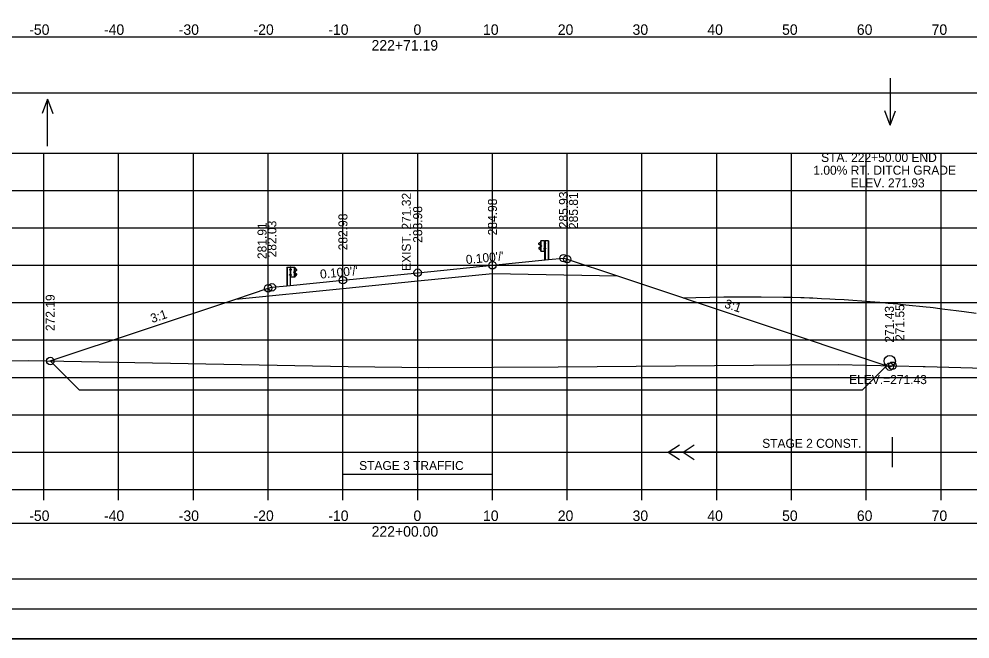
# Model space of a CAD drawing. Extents: x 4667 to 1632277, y -2100 to 724501.
# Drawn here: x 5723.9 to 5851.1, y -470.4 to -387.5 of the extents above; entities that cross this region are included whole.
import ezdxf

# ---------------------------------------------------------------- set-up
doc = ezdxf.new("R2010")
doc.units = 0
for name, color, linetype in [('R_Alt Surface', 7, 'Continuous'), ('R_Axis', 7, 'Continuous'), ('R_Axis Annot', 7, 'Continuous'), ('R_Border', 7, 'Continuous'), ('R_Draft', 7, 'Continuous'), ('R_Exist Surface', 7, 'Continuous'), ('R_Fin Surface', 7, 'Continuous'), ('R_Fin Surface Annot', 7, 'Continuous'), ('R_Grid', 7, 'Continuous'), ('R_No Plot', 7, 'Continuous'), ('R_Proposed CofA', 7, 'Continuous'), ('R_ROW', 7, 'Continuous'), ('R_Temp Easement', 7, 'Continuous'), ('R_Water', 7, 'Continuous'), ('R_Water Annot', 7, 'Continuous')]:
    doc.layers.add(name, color=color, linetype=linetype)

msp = doc.modelspace()

# ---------------------------------------------------------------- linework, layer by layer
at = {"layer": 'R_Alt Surface'}
msp.add_lwpolyline([(5752.86, -424.95), (5767.18, -423.52), (5777.18, -422.52), (5787.18, -421.52), (5803.91, -421.85)], dxfattribs=at)
at = {"layer": 'R_Axis'}
for p, q in [((5667.18, -450.42), (5947.18, -450.42)), ((5727.18, -451.82), (5727.18, -450.42)), ((5737.18, -451.82), (5737.18, -450.42)), ((5747.18, -451.82), (5747.18, -450.42)), ((5757.18, -451.82), (5757.18, -450.42)), ((5767.18, -451.82), (5767.18, -450.42)), ((5777.18, -451.82), (5777.18, -450.42)), ((5787.18, -451.82), (5787.18, -450.42)), ((5797.18, -451.82), (5797.18, -450.42)), ((5807.18, -451.82), (5807.18, -450.42)), ((5817.18, -451.82), (5817.18, -450.42)), ((5827.18, -451.82), (5827.18, -450.42)), ((5837.18, -451.82), (5837.18, -450.42)), ((5847.18, -451.82), (5847.18, -450.42))]:
    msp.add_line(p, q, dxfattribs=at)
at = {"layer": 'R_Border'}
msp.add_line((5964.36, -466.42), (5648.18, -466.42), dxfattribs=at)
at = {"layer": 'R_Draft'}
for p, q in [((5793.66, -418.53), (5793.66, -417.17)), ((5794.16, -417.17), (5794.17, -417.17)), ((5794.16, -417.17), (5794.23, -417.17)), ((5794.19, -419.68), (5794.19, -417.17)), ((5794.65, -417.17), (5794.65, -419.68)), ((5794.68, -417.17), (5794.68, -419.68)), ((5793.51, -418.33), (5793.38, -418.22)), ((5793.39, -417.49), (5793.52, -417.38)), ((5793.56, -417.73), (5793.39, -417.63)), ((5793.4, -417.5), (5793.53, -417.4)), ((5793.57, -417.71), (5793.4, -417.61)), ((5793.52, -418.32), (5793.4, -418.21)), ((5793.41, -418.07), (5793.57, -417.97)), ((5793.42, -418.09), (5793.58, -417.99)), ((5793.62, -418.39), (5793.51, -418.33)), ((5793.52, -417.38), (5793.63, -417.32)), ((5793.63, -418.37), (5793.52, -418.32)), ((5793.53, -417.4), (5793.62, -417.35)), ((5793.6, -417.91), (5793.6, -417.78)), ((5793.62, -417.91), (5793.62, -417.78)), ((5793.67, -417.91), (5793.67, -417.79)), ((5793.67, -417.79), (5793.72, -417.79)), ((5793.67, -417.82), (5793.72, -417.82)), ((5793.67, -417.88), (5793.72, -417.88)), ((5793.67, -417.88), (5793.72, -417.88)), ((5793.67, -417.91), (5793.72, -417.91)), ((5793.73, -417.9), (5793.73, -417.8)), ((5794.15, -417.47), (5794.1, -417.47)), ((5794.1, -417.47), (5794.1, -417.6)), ((5794.1, -417.54), (5794.16, -417.54)), ((5794.15, -417.6), (5794.1, -417.6)), ((5794.1, -418.28), (5794.1, -418.16)), ((5794.1, -418.16), (5794.15, -418.16)), ((5794.1, -418.22), (5794.16, -418.22)), ((5794.1, -418.28), (5794.15, -418.28)), ((5794.23, -417.59), (5794.23, -417.47)), ((5794.23, -417.47), (5794.28, -417.47)), ((5794.23, -417.5), (5794.28, -417.5)), ((5794.23, -417.56), (5794.27, -417.56)), ((5794.23, -417.56), (5794.28, -417.56)), ((5794.23, -417.59), (5794.28, -417.59)), ((5794.24, -418.28), (5794.24, -418.16)), ((5794.24, -418.16), (5794.29, -418.16)), ((5794.24, -418.19), (5794.29, -418.19)), ((5794.24, -418.25), (5794.28, -418.25)), ((5794.24, -418.25), (5794.29, -418.25)), ((5794.24, -418.28), (5794.29, -418.28)), ((5794.28, -417.58), (5794.28, -417.48)), ((5794.29, -418.27), (5794.29, -418.17)), ((5794.16, -418.53), (5794.19, -418.53)), ((5759.68, -420.67), (5759.68, -423.18)), ((5759.71, -420.67), (5759.71, -423.18)), ((5760.08, -421.08), (5760.08, -420.98)), ((5760.14, -420.97), (5760.09, -420.97)), ((5760.14, -421), (5760.09, -421)), ((5760.21, -420.67), (5760.14, -420.67)), ((5760.14, -421.09), (5760.14, -420.97)), ((5760.18, -423.18), (5760.18, -420.67)), ((5760.21, -420.67), (5760.2, -420.67)), ((5760.22, -420.97), (5760.27, -420.97)), ((5760.27, -420.97), (5760.27, -421.1)), ((5760.71, -422.03), (5760.71, -420.67)), ((5760.85, -420.88), (5760.74, -420.82)), ((5760.84, -420.9), (5760.75, -420.85)), ((5760.97, -421), (5760.84, -420.9)), ((5760.98, -420.99), (5760.85, -420.88)), ((5760.07, -421.77), (5760.07, -421.67)), ((5760.13, -421.66), (5760.08, -421.66)), ((5760.13, -421.69), (5760.08, -421.69)), ((5760.13, -421.75), (5760.08, -421.75)), ((5760.13, -421.78), (5760.08, -421.78)), ((5760.14, -421.06), (5760.09, -421.06)), ((5760.14, -421.09), (5760.09, -421.09)), ((5760.13, -421.75), (5760.09, -421.75)), ((5760.14, -421.06), (5760.1, -421.06)), ((5760.13, -421.78), (5760.13, -421.66)), ((5760.21, -422.03), (5760.17, -422.03)), ((5760.26, -421.04), (5760.21, -421.04)), ((5760.26, -421.72), (5760.21, -421.72)), ((5760.22, -421.1), (5760.27, -421.1)), ((5760.27, -421.66), (5760.22, -421.66)), ((5760.27, -421.78), (5760.22, -421.78)), ((5760.27, -421.78), (5760.27, -421.66)), ((5760.64, -421.4), (5760.64, -421.3)), ((5760.7, -421.29), (5760.65, -421.29)), ((5760.7, -421.32), (5760.65, -421.32)), ((5760.7, -421.38), (5760.65, -421.38)), ((5760.7, -421.38), (5760.65, -421.38)), ((5760.7, -421.41), (5760.65, -421.41)), ((5760.7, -421.41), (5760.7, -421.29)), ((5760.74, -421.87), (5760.84, -421.82)), ((5760.74, -421.89), (5760.86, -421.83)), ((5760.75, -421.41), (5760.75, -421.28)), ((5760.77, -421.41), (5760.77, -421.28)), ((5760.79, -421.21), (5760.97, -421.11)), ((5760.94, -421.59), (5760.79, -421.49)), ((5760.96, -421.57), (5760.8, -421.47)), ((5760.81, -421.23), (5760.98, -421.13)), ((5760.84, -421.82), (5760.97, -421.71)), ((5760.86, -421.83), (5760.98, -421.72))]:
    msp.add_line(p, q, dxfattribs=at)
for points in [[(5793.63, -417.17), (5793.64, -418.53), (5794.16, -418.53), (5794.16, -417.17)], [(5793.67, -417.77), (5793.67, -417.94), (5793.66, -417.94), (5793.66, -417.77)], [(5793.73, -417.82), (5793.73, -417.88), (5793.76, -417.88), (5793.76, -417.82)], [(5794.1, -417.47), (5794.1, -417.6), (5794.16, -417.6), (5794.16, -417.47)], [(5794.1, -418.16), (5794.1, -418.28), (5794.16, -418.28), (5794.16, -418.16)], [(5794.23, -417.45), (5794.23, -417.62), (5794.22, -417.62), (5794.22, -417.45)], [(5794.24, -418.14), (5794.24, -418.31), (5794.23, -418.31), (5794.23, -418.14)], [(5794.29, -417.5), (5794.29, -417.56), (5794.31, -417.56), (5794.31, -417.5)], [(5794.3, -418.19), (5794.3, -418.25), (5794.32, -418.25), (5794.32, -418.19)], [(5760.08, -421), (5760.08, -421.06), (5760.06, -421.06), (5760.06, -421)], [(5760.14, -420.95), (5760.14, -421.12), (5760.15, -421.12), (5760.15, -420.95)], [(5760.73, -420.67), (5760.73, -422.03), (5760.21, -422.03), (5760.21, -420.67)], [(5760.26, -420.97), (5760.26, -421.1), (5760.21, -421.1), (5760.21, -420.97)], [(5760.07, -421.69), (5760.07, -421.75), (5760.05, -421.75), (5760.05, -421.69)], [(5760.13, -421.64), (5760.13, -421.81), (5760.14, -421.81), (5760.14, -421.64)], [(5760.26, -421.66), (5760.26, -421.78), (5760.21, -421.78), (5760.21, -421.66)], [(5760.64, -421.32), (5760.64, -421.38), (5760.61, -421.38), (5760.61, -421.32)], [(5760.69, -421.27), (5760.69, -421.44), (5760.7, -421.44), (5760.7, -421.27)]]:
    msp.add_lwpolyline(points, close=True, dxfattribs=at)
for points in [[(5794.68, -417.17), (5794.23, -417.17), (5794.23, -419.68)], [(5759.68, -420.67), (5760.14, -420.67), (5760.14, -423.18)]]:
    msp.add_lwpolyline(points, dxfattribs=at)
for centre, radius, start, end in [((5793.43, -417.55), 0.0856, 122.0217, 240.7501), ((5793.47, -418.16), 0.109, 120.88, 214.7816), ((5793.43, -417.55), 0.062, 122.0217, 240.7501), ((5793.47, -418.16), 0.0854, 120.88, 214.7816), ((5793.53, -417.79), 0.0622, 4.9556, 61.894), ((5793.6, -417.86), 0.0453, 93.9303, 257.0446), ((5793.53, -417.79), 0.0865, 4.9556, 61.894), ((5793.55, -417.92), 0.0462, 293.1464, 8.2196), ((5793.55, -417.92), 0.0703, 293.1464, 8.2196), ((5793.71, -417.81), 0.022, 317.7756, 45.4255), ((5793.64, -417.85), 0.0922, 339.7423, 20.2577), ((5793.7, -417.9), 0.025, 323.3766, 39.0666), ((5794.26, -417.48), 0.022, 317.7756, 45.4255), ((5794.19, -417.53), 0.0922, 339.7423, 20.2577), ((5794.26, -417.58), 0.025, 323.3766, 39.0666), ((5794.27, -418.17), 0.022, 317.7756, 45.4255), ((5794.2, -418.22), 0.0922, 339.7423, 20.2577), ((5794.27, -418.27), 0.025, 323.3766, 39.0666), ((5760.11, -420.98), 0.022, 134.5745, 222.2244), ((5760.18, -421.03), 0.0922, 159.7423, 200.2577), ((5760.94, -421.05), 0.062, 299.2499, 57.9783), ((5760.94, -421.05), 0.0856, 299.2499, 57.9783), ((5760.1, -421.67), 0.022, 134.5745, 222.2244), ((5760.17, -421.72), 0.0922, 159.7423, 200.2577), ((5760.1, -421.77), 0.025, 140.9334, 216.6234), ((5760.11, -421.08), 0.025, 140.9334, 216.6234), ((5760.66, -421.31), 0.022, 134.5745, 222.2244), ((5760.73, -421.35), 0.0922, 159.7423, 200.2577), ((5760.67, -421.4), 0.025, 140.9334, 216.6234), ((5760.84, -421.29), 0.0865, 118.106, 175.0444), ((5760.82, -421.42), 0.0703, 171.7804, 246.8536), ((5760.84, -421.29), 0.0622, 118.106, 175.0444), ((5760.77, -421.36), 0.0453, 282.9554, 86.0697), ((5760.82, -421.42), 0.0462, 171.7804, 246.8536), ((5760.9, -421.66), 0.0854, 325.2184, 59.12), ((5760.9, -421.66), 0.109, 325.2184, 59.12)]:
    msp.add_arc(centre, radius, start, end, dxfattribs=at)
at = {"layer": 'R_Exist Surface'}
msp.add_lwpolyline([(5667.18, -433.36), (5673.31, -433.31), (5706.47, -433.32), (5708.5, -433.31), (5725.08, -433.17), (5767.9, -433.95), (5778.63, -434.12), (5795.98, -434), (5822.11, -433.78), (5826.91, -433.74), (5833.41, -433.7), (5844.81, -433.96), (5845.05, -433.97), (5879.94, -434.93)], dxfattribs=at)
at = {"layer": 'R_Fin Surface'}
for points in [[(5728.03, -433.23), (5752.86, -424.95), (5757.18, -423.51), (5757.68, -423.38), (5759.68, -423.18), (5767.18, -422.43), (5777.18, -421.43), (5787.18, -420.43), (5794.68, -419.68), (5796.68, -419.48), (5797.18, -419.61), (5803.91, -421.85), (5840.32, -433.99), (5840.68, -433.87)], [(5812.7, -424.78), (5814.38, -424.74), (5818.11, -424.65), (5823.13, -424.67), (5826.12, -424.69), (5827.28, -424.71), (5828.44, -424.74), (5828.89, -424.76), (5829.58, -424.79), (5830.05, -424.8), (5831.18, -424.86), (5832.3, -424.93), (5833.03, -424.96), (5834.24, -425.02), (5835.37, -425.11), (5836.6, -425.18), (5837.72, -425.28), (5838.98, -425.37), (5840.09, -425.48), (5841.38, -425.59), (5842.49, -425.72), (5845.19, -425.99), (5845.71, -426.04), (5846.12, -426.09), (5847.03, -426.2), (5847.71, -426.29), (5849.22, -426.48), (5850.29, -426.63), (5851.88, -426.85)]]:
    msp.add_lwpolyline(points, dxfattribs=at)
at = {"layer": 'R_Grid'}
for p, q in [((5667.18, -405.42), (5947.18, -405.42)), ((5727.18, -450.42), (5727.18, -405.42)), ((5737.18, -450.42), (5737.18, -405.42)), ((5747.18, -450.42), (5747.18, -405.42)), ((5757.18, -450.42), (5757.18, -405.42)), ((5767.18, -450.42), (5767.18, -405.42)), ((5777.18, -450.42), (5777.18, -405.42)), ((5787.18, -450.42), (5787.18, -405.42)), ((5797.18, -450.42), (5797.18, -405.42)), ((5807.18, -450.42), (5807.18, -405.42)), ((5817.18, -450.42), (5817.18, -405.42)), ((5827.18, -450.42), (5827.18, -405.42)), ((5837.18, -450.42), (5837.18, -405.42)), ((5847.18, -450.42), (5847.18, -405.42)), ((5667.18, -410.42), (5947.18, -410.42)), ((5667.18, -415.42), (5947.18, -415.42)), ((5667.18, -420.42), (5947.18, -420.42)), ((5667.18, -425.42), (5947.18, -425.42)), ((5667.18, -430.42), (5947.18, -430.42)), ((5667.18, -435.42), (5947.18, -435.42)), ((5667.18, -440.42), (5947.18, -440.42)), ((5667.18, -445.42), (5947.18, -445.42)), ((5667.18, -450.42), (5947.18, -450.42))]:
    msp.add_line(p, q, dxfattribs=at)
at = {"layer": 'R_No Plot'}
msp.add_line((5635.78, -470.4), (5969.12, -470.4), dxfattribs=at)
for points in [[(5635.78, -257.06), (5969.12, -257.06), (5969.12, -470.4), (5635.78, -470.4)], [(5882.1, -260.96), (5901.72, -260.96), (5901.72, -270.84), (5917.84, -270.84), (5941.04, -270.84), (5941.04, -295.17), (5964.36, -295.17), (5964.36, -466.42), (5648.18, -466.42), (5648.18, -260.96)]]:
    msp.add_lwpolyline(points, close=True, dxfattribs=at)
for centre in [(5796.68, -419.48), (5797.18, -419.61), (5777.18, -421.43), (5787.18, -420.43), (5767.18, -422.43), (5757.18, -423.51), (5757.68, -423.38), (5728.03, -433.23), (5840.32, -433.99), (5840.68, -433.87)]:
    msp.add_circle(centre, 0.5, dxfattribs=at)
at = {"layer": 'R_Proposed CofA'}
for p, q in [((5810.68, -445.42), (5812.18, -444.42)), ((5812.68, -445.42), (5814.18, -444.42)), ((5810.68, -445.42), (5812.18, -446.42)), ((5812.68, -445.42), (5814.18, -446.42))]:
    msp.add_line(p, q, dxfattribs=at)
for points in [[(5667.23, -397.36), (5947.13, -397.36), (5947.13, -389.94), (5667.23, -389.94)], [(5667.23, -462.36), (5947.13, -462.36), (5947.13, -454.94), (5667.23, -454.94)]]:
    msp.add_lwpolyline(points, close=True, dxfattribs=at)
at = {"layer": 'R_ROW'}
for p, q in [((5728.03, -433.23), (5731.9, -437.1)), ((5839.91, -433.85), (5836.66, -437.1)), ((5731.9, -437.1), (5836.66, -437.1))]:
    msp.add_line(p, q, dxfattribs=at)
at = {"layer": 'R_Temp Easement'}
for p, q in [((5840.68, -447.42), (5840.68, -443.42)), ((5767.18, -450.42), (5767.18, -446.42)), ((5787.18, -450.42), (5787.18, -446.42)), ((5840.68, -445.42), (5810.68, -445.42)), ((5787.18, -448.42), (5767.18, -448.42))]:
    msp.add_line(p, q, dxfattribs=at)
at = {"layer": 'R_Water'}
msp.add_circle((5840.32, -433.24), 0.75, dxfattribs=at)
at = {"layer": 'R_Water Annot'}
for p, q in [((5840.38, -395.42), (5840.38, -401.7)), ((5727.66, -398.23), (5726.96, -400.16)), ((5727.66, -404.52), (5727.66, -398.23)), ((5727.66, -398.23), (5728.36, -400.16)), ((5840.38, -401.7), (5839.68, -399.78)), ((5840.38, -401.7), (5841.08, -399.78))]:
    msp.add_line(p, q, dxfattribs=at)

# ---------------------------------------------------------------- texts
at = {"layer": 'R_Axis Annot'}
for s, p in [('-50', (5725.22, -389.62)), ('-40', (5735.22, -389.62)), ('-30', (5745.22, -389.62)), ('-20', (5755.22, -389.62)), ('-10', (5765.22, -389.62)), ('0', (5776.62, -389.62)), ('10', (5785.92, -389.62)), ('20', (5795.92, -389.62)), ('30', (5805.92, -389.62)), ('40', (5815.92, -389.62)), ('50', (5825.92, -389.62)), ('60', (5835.92, -389.62)), ('70', (5845.92, -389.62)), ('222+71.19', (5771.01, -391.72)), ('-50', (5725.22, -454.62)), ('-40', (5735.22, -454.62)), ('-30', (5745.22, -454.62)), ('-20', (5755.22, -454.62)), ('-10', (5765.22, -454.62)), ('0', (5776.62, -454.62)), ('10', (5785.92, -454.62)), ('20', (5795.92, -454.62)), ('30', (5805.92, -454.62)), ('40', (5815.92, -454.62)), ('50', (5825.92, -454.62)), ('60', (5835.92, -454.62)), ('70', (5845.92, -454.62)), ('222+00.00', (5771.02, -456.72))]:
    msp.add_text(s, height=1.4, dxfattribs=at).set_placement(p)
at = {"layer": 'R_Fin Surface Annot'}
for s, rotation, p in [('285.93', 90, (5797.28, -415.48)), ('285.81', 90, (5798.61, -415.59)), ('284.98', 90, (5787.78, -416.43)), ('283.98', 90, (5777.78, -417.43)), ('282.03', 90, (5758.28, -419.38)), ('282.98', 90, (5767.78, -418.43)), ('281.91', 90, (5756.96, -419.6)), ("0.100'/'", 5.7106, (5783.68, -420.28)), ("0.100'/'", 5.7106, (5764.18, -422.23)), ('272.19', 90, (5728.63, -429.23)), ('3:1', 341.5651, (5818.12, -426.06)), ('271.43', 90, (5840.87, -430.78)), ('271.55', 90, (5842.28, -430.55)), ('3:1', 18.4349, (5741.66, -428.16))]:
    msp.add_text(s, height=1.2, rotation=rotation, dxfattribs=at).set_placement(p)
at = {"layer": 'R_Temp Easement'}
msp.add_text('EXIST. 271.32', height=1.2, rotation=90, dxfattribs=at).set_placement((5776.26, -421.19))
for s, p in [('STAGE 2 CONST.', (5823.26, -444.84)), ('STAGE 3 TRAFFIC', (5769.35, -447.81))]:
    msp.add_text(s, height=1.1985, dxfattribs=at).set_placement(p)
at = {"layer": 'R_Water Annot'}
for s, p in [('STA. 222+50.00 END', (5831.14, -406.62)), ('1.00% RT. DITCH GRADE', (5830.1, -408.32)), ('ELEV. 271.93', (5835.09, -410.02)), ('ELEV.=271.43', (5834.89, -436.32))]:
    msp.add_text(s, height=1.2, dxfattribs=at).set_placement(p)

doc.saveas('drawing.dxf')
